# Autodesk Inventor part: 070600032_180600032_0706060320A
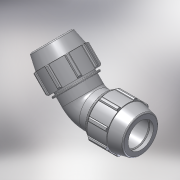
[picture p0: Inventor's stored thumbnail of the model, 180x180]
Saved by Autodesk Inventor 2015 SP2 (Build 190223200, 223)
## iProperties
Created: 2017-02
Part Number: 070600032_180600032_0706060320A
Material: PVC-Piping
Description: PLASSON 45° ELBOW 32-32
Document SubType Name: Modeling
Designer: KIM
Mass: 92.6774 g
Surface Area: 199.44 cm^2
Volume: 66.1981 cm^3
Density: 1.4 g/cm^3
Appearance: Smooth - White
Author: KIM
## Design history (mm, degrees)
derived "07060.ipt"
feature "Solid1::07060.ipt"
tag "TaggingFeature1"
body "Solid1"
other parameters: "d2" = 32, "d4" = 7.66667, "d5" = 23, "d7" = 64, "d9" = 13.14286, "d11" = 3.06667, "d13" = 120 deg, "d14" = 48, "d15" = 12 deg, "d16" = 55.68, "d18" = 1.6, "d19" = 35 deg, "d20" = 17.5 deg, "d21" = 59.52, "d23" = 0, "d25" = 360 deg, "d27" = 1.28, "d33" = 0.64, "d42" = 34.04, "d43" = 1.92, "d46" = 0.96, "d51" = 92, "d59" = 135 deg, "d63" = 67, "d67" = 48, "d68" = 3.06667, "d72" = 1.5, "d73" = 0, "d74" = 0, "d_" = 32, "E_" = 64, "A_" = 92, "l_" = 67
